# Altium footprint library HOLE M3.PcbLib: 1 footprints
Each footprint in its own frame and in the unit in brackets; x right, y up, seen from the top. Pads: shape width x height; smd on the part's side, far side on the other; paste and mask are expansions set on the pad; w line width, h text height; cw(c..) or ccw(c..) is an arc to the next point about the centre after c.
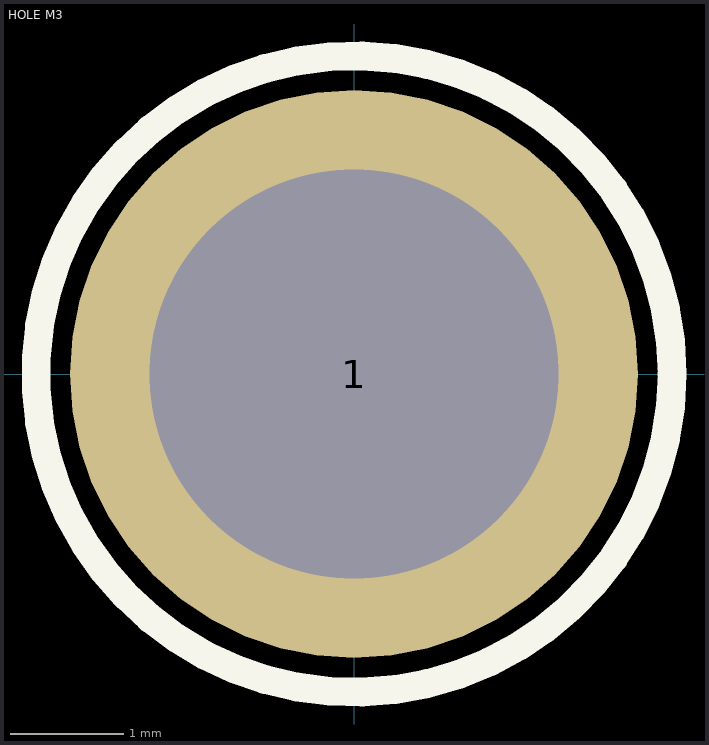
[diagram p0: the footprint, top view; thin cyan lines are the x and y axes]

## HOLE M3 [mm] "M3 X0.5 HOLE NO METAL"
height 2.4
pads (1):
  round 5 hole 3.6: 1(0,0)
Top Overlay:
  circle w0.254: c0,0 r2.8
M5 Assembly Top:
  text ".Designator" at -0.1,-0.1 h1.02
3D body: height 2.5, standoff 0, extent -4.356,-4.3 4.3,4.3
